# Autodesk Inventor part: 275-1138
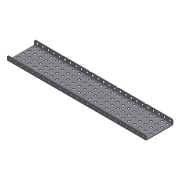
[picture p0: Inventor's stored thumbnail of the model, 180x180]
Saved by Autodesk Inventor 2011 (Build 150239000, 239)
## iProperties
Company: Autodesk Inc.
Created: 2005-08
Part Number: 275-1138
Document SubType Name: Sheet Metal
Designer: Autodesk Inc.
Density: 1 g/cm^3
Sheet Metal Rule: Default
Sheet Metal Width: 0.000 in
Sheet Metal Length: 0.000 in
Sheet Metal Area: 0.000 in^2
Catalog Web Link: http://www.vexrobotics.com/products/accessories/structure/c-channel.html
Vendor: Innovation First, Inc.
Description: VEX C-channel has holes on 0.500" increments. This structural member is perfect for building bigger robots. Excellent strength
Author: Autodesk Inc.
Title: VEX Robotics Kit of Parts
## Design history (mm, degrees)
node "Face1"
  sketch "Sketch1"
    geometry: L1 (-38.442, 14.458)-(275.248, 14.458); L2 (277.153, 12.553)-(277.153, 3.028); L3 (277.153, 3.028)-(-40.347, 3.028); L4 (-40.347, 3.028)-(-40.347, 12.553); L5 (-40.347, 12.553)-(-38.442, 14.458); L6 (275.248, 14.458)-(277.153, 12.553); 2 further points
    constraints: 16 end point, 4 point on line, 2 parallel, 1 horizontal, 1 perpendicular
    dimensions: "d5" = 11.43 distance of L3.end point (-40.347, 14.458); "d64" = 317.5 distance of L2.end L3.end; "d98" = 1.905 distance of L4.end point (-40.347, 14.458); "d99" = 1.905 distance of L1.start point (-40.347, 14.458) (= d98); "d102" = 1.905 distance of L1.end point (277.153, 14.458); "d103" = 1.905 distance of L2.start point (277.153, 14.458) (= d102)
node "Flange3"
sketch "Sketch10" dims "d134" = 25.4
  geometry: L1 (0, 0)-(0, 29.616) reference; L2 (0, 32.639)-(0, 28.829); L3 (0, 28.829)-(1.905, 30.734); L4 (1.905, 30.734)-(0, 32.639); L5 (317.5, 29.616)-(0, 29.616) reference; L6 (0, 32.639)-(-1.905, 30.734); L7 (-1.905, 30.734)-(0, 28.829); L8 (63.5, 32.639)-(61.595, 30.734); L9 (61.595, 30.734)-(63.5, 28.829); L10 (65.405, 30.734)-(63.5, 32.639); L11 (63.5, 28.829)-(65.405, 30.734); L12 (127, 32.639)-(125.095, 30.734); L13 (125.095, 30.734)-(127, 28.829); L14 (128.905, 30.734)-(127, 32.639); L15 (127, 28.829)-(128.905, 30.734); L16 (190.5, 32.639)-(188.595, 30.734); L17 (188.595, 30.734)-(190.5, 28.829); L18 (192.405, 30.734)-(190.5, 32.639); L19 (190.5, 28.829)-(192.405, 30.734); L20 (254, 32.639)-(252.095, 30.734); L21 (252.095, 30.734)-(254, 28.829); L22 (255.905, 30.734)-(254, 32.639); L23 (254, 28.829)-(255.905, 30.734); 1 further point
  constraints: 42 end point, 2 parallel, 1 collinear, 1 horizontal, 1 perpendicular, 1 point on line, 32 other
  dimensions: "d124" = 3.81 distance of L2.start L2.end; "d127" = 1.905 distance from line of L2 L3.end; "d131" = 63.5 distance of L2.start L8.start; "d160" = 1.1176 distance from line of L6.end L5
cut "Cut5" sketch "Sketch10" dims "d125" = 1.27 (= Thickness), "d126" = 0
sketch "Sketch11" dims "d143" = 25.4
  geometry: L1 (0, 0)-(313.69, 0) reference; L2 (-1.905, -9.296)-(-1.905, -1.905) reference; L3 (59.69, 0)-(61.595, -1.905); L4 (61.595, -1.905)-(63.5, 0); L5 (63.5, 0)-(61.595, 1.905); L6 (61.595, 1.905)-(59.69, 0); L7 (125.095, -1.905)-(127, 0); L8 (127, 0)-(125.095, 1.905); L9 (125.095, 1.905)-(123.19, 0); L10 (123.19, 0)-(125.095, -1.905); L11 (188.595, -1.905)-(190.5, 0); L12 (190.5, 0)-(188.595, 1.905); L13 (188.595, 1.905)-(186.69, 0); L14 (186.69, 0)-(188.595, -1.905); L15 (252.095, -1.905)-(254, 0); L16 (254, 0)-(252.095, 1.905); L17 (252.095, 1.905)-(250.19, 0); L18 (250.19, 0)-(252.095, -1.905); 1 further point
  constraints: 32 end point, 2 parallel, 2 perpendicular, 2 point on line, 1 horizontal, 24 other
  dimensions: "d136" = 1.905 horizontal distance of L5.end L3.start; "d137" = 63.5 distance from line of L5.end L2; "d140" = 63.5 distance of L4.end L7.end
cut "Cut6" sketch "Sketch11" dims "d145" = 1.27 (= Thickness), "d146" = 0
sketch "Sketch12" dims "d156" = 25.4
  geometry: L1 (1.905, 9.296)-(61.595, 9.296) reference; L2 (0, 0)-(0, 7.391) reference; L3 (4.064, 6.502)-(8.636, 6.502); L4 (8.636, 6.502)-(8.636, 1.93); L5 (8.636, 1.93)-(4.064, 1.93); L6 (4.064, 1.93)-(4.064, 6.502); L7 (16.764, 6.502)-(21.336, 6.502); L8 (21.336, 6.502)-(21.336, 1.93); L9 (21.336, 1.93)-(16.764, 1.93); L10 (16.764, 1.93)-(16.764, 6.502); L11 (29.464, 6.502)-(34.036, 6.502); L12 (34.036, 6.502)-(34.036, 1.93); L13 (34.036, 1.93)-(29.464, 1.93); L14 (29.464, 1.93)-(29.464, 6.502); L15 (42.164, 6.502)-(46.736, 6.502); L16 (46.736, 6.502)-(46.736, 1.93); L17 (46.736, 1.93)-(42.164, 1.93); L18 (42.164, 1.93)-(42.164, 6.502); L19 (54.864, 6.502)-(59.436, 6.502); L20 (59.436, 6.502)-(59.436, 1.93); L21 (59.436, 1.93)-(54.864, 1.93); L22 (54.864, 1.93)-(54.864, 6.502); L23 (67.564, 6.502)-(72.136, 6.502); L24 (72.136, 6.502)-(72.136, 1.93); L25 (72.136, 1.93)-(67.564, 1.93); L26 (67.564, 1.93)-(67.564, 6.502); L27 (80.264, 6.502)-(84.836, 6.502); L28 (84.836, 6.502)-(84.836, 1.93); L29 (84.836, 1.93)-(80.264, 1.93); L30 (80.264, 1.93)-(80.264, 6.502); L31 (92.964, 6.502)-(97.536, 6.502); L32 (97.536, 6.502)-(97.536, 1.93); L33 (97.536, 1.93)-(92.964, 1.93); L34 (92.964, 1.93)-(92.964, 6.502); L35 (105.664, 6.502)-(110.236, 6.502); L36 (110.236, 6.502)-(110.236, 1.93); L37 (110.236, 1.93)-(105.664, 1.93); L38 (105.664, 1.93)-(105.664, 6.502); L39 (118.364, 6.502)-(122.936, 6.502); L40 (122.936, 6.502)-(122.936, 1.93); L41 (122.936, 1.93)-(118.364, 1.93); L42 (118.364, 1.93)-(118.364, 6.502); L43 (131.064, 6.502)-(135.636, 6.502); L44 (135.636, 6.502)-(135.636, 1.93); L45 (135.636, 1.93)-(131.064, 1.93); L46 (131.064, 1.93)-(131.064, 6.502); L47 (143.764, 6.502)-(148.336, 6.502); L48 (148.336, 6.502)-(148.336, 1.93); L49 (148.336, 1.93)-(143.764, 1.93); L50 (143.764, 1.93)-(143.764, 6.502); L51 (156.464, 6.502)-(161.036, 6.502); L52 (161.036, 6.502)-(161.036, 1.93); L53 (161.036, 1.93)-(156.464, 1.93); L54 (156.464, 1.93)-(156.464, 6.502); L55 (169.164, 6.502)-(173.736, 6.502); L56 (173.736, 6.502)-(173.736, 1.93); L57 (173.736, 1.93)-(169.164, 1.93); L58 (169.164, 1.93)-(169.164, 6.502); L59 (181.864, 6.502)-(186.436, 6.502); L60 (186.436, 6.502)-(186.436, 1.93); L61 (186.436, 1.93)-(181.864, 1.93); L62 (181.864, 1.93)-(181.864, 6.502); L63 (194.564, 6.502)-(199.136, 6.502); L64 (199.136, 6.502)-(199.136, 1.93)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
  constraints: 200 end point, 2 horizontal, 2 parallel, 1 perpendicular, 192 other
  dimensions: "d147" = 2.794 distance between parallel lines of L1 L3; "d148" = 4.572 distance of L5.end L3.start; "d149" = 4.572 distance of L3.start L3.end; "d150" = 4.064 distance between parallel lines of L2 L6; "d153" = 12.7 distance of L3.start L7.start
cut "Cut7" sketch "Sketch12" dims "d158" = 1.27 (= Thickness), "d159" = 0
sketch "Sketch13"
  geometry: L1 (62.713, 29.616)-(0, 29.616) reference; L2 (0, 0)-(0, 29.616) reference; L3 (4.064, 27.686)-(8.636, 27.686); L4 (8.636, 27.686)-(8.636, 23.114); L5 (8.636, 23.114)-(4.064, 23.114); L6 (4.064, 23.114)-(4.064, 27.686); L7 (0, 30.48)-(62.712, 30.48) reference; L8 (8.636, 14.986)-(8.636, 10.414); L9 (4.064, 14.986)-(8.636, 14.986); L10 (8.636, 10.414)-(4.064, 10.414); L11 (4.064, 10.414)-(4.064, 14.986); L12 (8.636, 2.286)-(8.636, -2.286); L13 (4.064, 2.286)-(8.636, 2.286); L14 (8.636, -2.286)-(4.064, -2.286); L15 (4.064, -2.286)-(4.064, 2.286); L16 (21.336, 27.686)-(21.336, 23.114); L17 (16.764, 27.686)-(21.336, 27.686); L18 (21.336, 23.114)-(16.764, 23.114); L19 (16.764, 23.114)-(16.764, 27.686); L20 (21.336, 14.986)-(21.336, 10.414); L21 (16.764, 14.986)-(21.336, 14.986); L22 (21.336, 10.414)-(16.764, 10.414); L23 (16.764, 10.414)-(16.764, 14.986); L24 (21.336, 2.286)-(21.336, -2.286); L25 (16.764, 2.286)-(21.336, 2.286); L26 (21.336, -2.286)-(16.764, -2.286); L27 (16.764, -2.286)-(16.764, 2.286); L28 (34.036, 27.686)-(34.036, 23.114); L29 (29.464, 27.686)-(34.036, 27.686); L30 (34.036, 23.114)-(29.464, 23.114); L31 (29.464, 23.114)-(29.464, 27.686); L32 (34.036, 14.986)-(34.036, 10.414); L33 (29.464, 14.986)-(34.036, 14.986); L34 (34.036, 10.414)-(29.464, 10.414); L35 (29.464, 10.414)-(29.464, 14.986); L36 (34.036, 2.286)-(34.036, -2.286); L37 (29.464, 2.286)-(34.036, 2.286); L38 (34.036, -2.286)-(29.464, -2.286); L39 (29.464, -2.286)-(29.464, 2.286); L40 (46.736, 27.686)-(46.736, 23.114); L41 (42.164, 27.686)-(46.736, 27.686); L42 (46.736, 23.114)-(42.164, 23.114); L43 (42.164, 23.114)-(42.164, 27.686); L44 (46.736, 14.986)-(46.736, 10.414); L45 (42.164, 14.986)-(46.736, 14.986); L46 (46.736, 10.414)-(42.164, 10.414); L47 (42.164, 10.414)-(42.164, 14.986); L48 (46.736, 2.286)-(46.736, -2.286); L49 (42.164, 2.286)-(46.736, 2.286); L50 (46.736, -2.286)-(42.164, -2.286); L51 (42.164, -2.286)-(42.164, 2.286); L52 (59.436, 27.686)-(59.436, 23.114); L53 (54.864, 27.686)-(59.436, 27.686); L54 (59.436, 23.114)-(54.864, 23.114); L55 (54.864, 23.114)-(54.864, 27.686); L56 (59.436, 14.986)-(59.436, 10.414); L57 (54.864, 14.986)-(59.436, 14.986); L58 (59.436, 10.414)-(54.864, 10.414); L59 (54.864, 10.414)-(54.864, 14.986); L60 (59.436, 2.286)-(59.436, -2.286); L61 (54.864, 2.286)-(59.436, 2.286); L62 (59.436, -2.286)-(54.864, -2.286); L63 (54.864, -2.286)-(54.864, 2.286); L64 (72.136, 27.686)-(72.136, 23.114)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; 1 further point
  constraints: 600 end point, 2 horizontal, 2 parallel, 1 perpendicular, 1 vertical, 592 other
  dimensions: "d161" = 4.064 distance between parallel lines of L2 L6; "d162" = 4.572 distance of L5.end L3.start; "d163" = 4.572 distance of L4.end L5.end; "d164" = 2.794 distance between parallel lines of L7 L3; "d167" = 12.7 distance of L3.end L8.start; "d170" = 12.7 distance of L3.end L16.start
cut "Cut8" sketch "Sketch13" dims "d173" = 1.27 (= Thickness), "d174" = 0
mirror "Mirror1"
body "Solid1"
face "Plate1" dims "Thickness" = 1.27
sketch "Sketch8"
  geometry: L1 (0, 31.75)-(-317.5, 31.75); L2 (-317.5, 31.75)-(-317.5, 0); 2 other entities
  constraints: 4 end point, 4 other
face "Plate4" dims "d107" = 1.27 (= BendReliefWidth), "d108" = 0.635 (= BendReliefDepth), "d109" = 2.54 (= MinimumRemnant), "d110" = 0.8636 (= BendRadius), "d111" = 31.75, "d112" = 90 deg, "d113" = 0.8636 (= BendRadius), "d114" = 5.08 (= CornerReliefSize), "d115" = 1.27 (= GapSize), "d116" = 1.27 (= JacobiRadiusSize), "SeamGap" = 0.00508, "Thickness" = 1.27
bend "Bend3" dims "d107" = 1.27 (= BendReliefWidth), "d108" = 0.635 (= BendReliefDepth), "d109" = 2.54 (= MinimumRemnant), "d110" = 0.8636 (= BendRadius), "d111" = 31.75, "d112" = 90 deg, "d113" = 0.8636 (= BendRadius), "SeamGap" = 0.00508, "Thickness" = 1.27
feature "Corner2" dims "d111" = 31.75, "d112" = 90 deg, "d114" = 5.08 (= CornerReliefSize), "d115" = 1.27 (= GapSize), "d116" = 1.27 (= JacobiRadiusSize)
other parameters: "BendRadius" = 0.8636, "BendReliefWidth" = 1.27 (= Thickness), "BendReliefDepth" = 0.635 (= 0.5 x Thickness), "CornerReliefSize" = 5.08 (= 4 x Thickness), "MinimumRemnant" = 2.54 (= 2 x Thickness), "TransitionRadius" = 0.8636 (= BendRadius), "d14" = 0.8636 (= BendRadius), "JacobiRadiusSize" = 1.27 (= Thickness), "GapSize" = 1.27 (= Thickness)
